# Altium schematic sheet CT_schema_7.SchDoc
size 287 x 160 mm
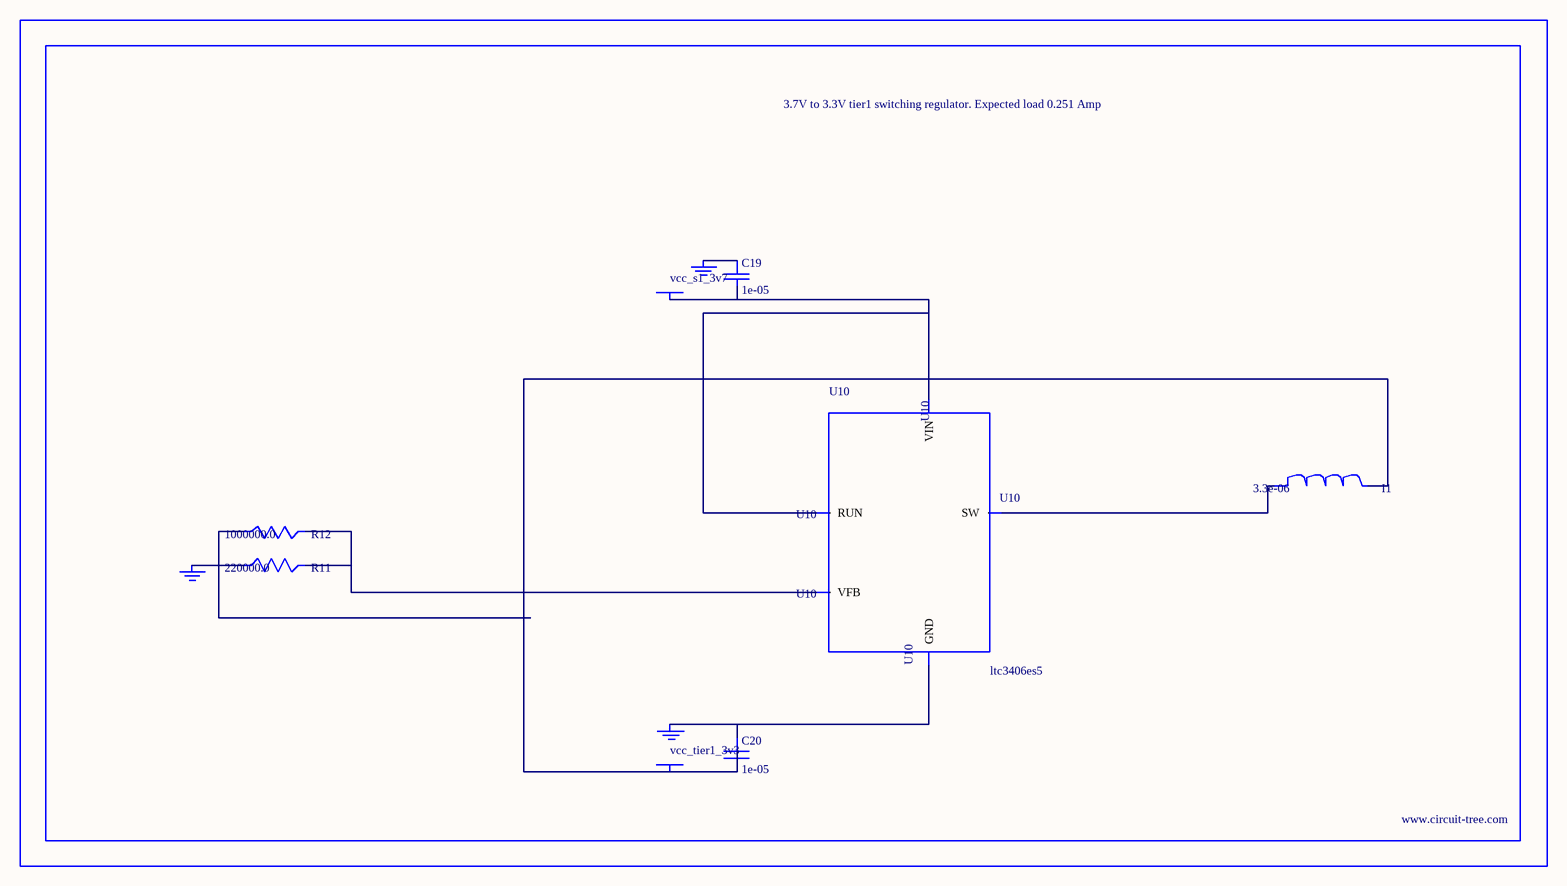
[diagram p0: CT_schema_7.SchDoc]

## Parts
BORDER6  (no value)
C19  1e-05  [C0805]
C20  1e-05  [C0805]
GND_INSTANCE_6_0  (no value)
GND_INSTANCE_6_1  (no value)
GND_INSTANCE_6_2  (no value)
I1  3.3e-06  [L0806]
POWER_INSTANCE_6_0  vcc_tier1_3v3
POWER_INSTANCE_6_1  vcc_s1_3v7
R11  220000.0  [R0603]
R12  1000000.0  [R0603]
U10  ltc3406es5  [TSOT-23-5]

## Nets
NetC19_1: C19.1 GND_INSTANCE_6_1.0(GND)
NetC19_2: C19.2 POWER_INSTANCE_6_1.0(PWR) U10.1(RUN) U10.4(VIN)
NetC20_1: C20.1 GND_INSTANCE_6_0.0(GND) U10.2(GND)
NetC20_2: C20.2 I1.2 POWER_INSTANCE_6_0.0(PWR) R12.1
NetGND_INSTANCE_6_2_0: GND_INSTANCE_6_2.0(GND) R11.1
NetI1_1: I1.1 U10.3(SW)
NetR11_2: R11.2 R12.2 U10.5(VFB)

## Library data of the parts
BORDER6 = BORDER_PAGE6
C19 C20 = C0805C106K8RACTU
GND_INSTANCE_6_0-GND_INSTANCE_6_2 = GND
I1 = L0806C3R3MDWIT
POWER_INSTANCE_6_0 POWER_INSTANCE_6_1 = PWR
R11 = RC0603JR-07220KL
R12 = RC0603JR-071ML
